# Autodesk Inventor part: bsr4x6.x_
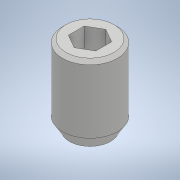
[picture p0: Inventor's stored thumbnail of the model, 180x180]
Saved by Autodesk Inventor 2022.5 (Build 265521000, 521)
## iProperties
Created: 2020-01
Part Number: bsr4x6.x_
Material: 一般
Document SubType Name: Modeling
Designer: ImaoCorp
Density: 1 g/cm^3
Appearance: 既定
Sending System: SOLIDWORKS 2018-2018316
MC: AMD64
MC_MODEL: Intel64 Family 6 Model 60 Stepping 3, GenuineIntel
OS: Windows_NT
FRU: Parasolid Version 30.0, build 310,  6- 8-2018
FORMAT: text
GUISE: transmit
KEY: bsr4x6
FILE: bsr4x6.x_t
DATE: Thu Jan 23 16:47:28 2020
Author: ImaoCorp
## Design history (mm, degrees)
feature "Base1"
node "ソリッド1"
